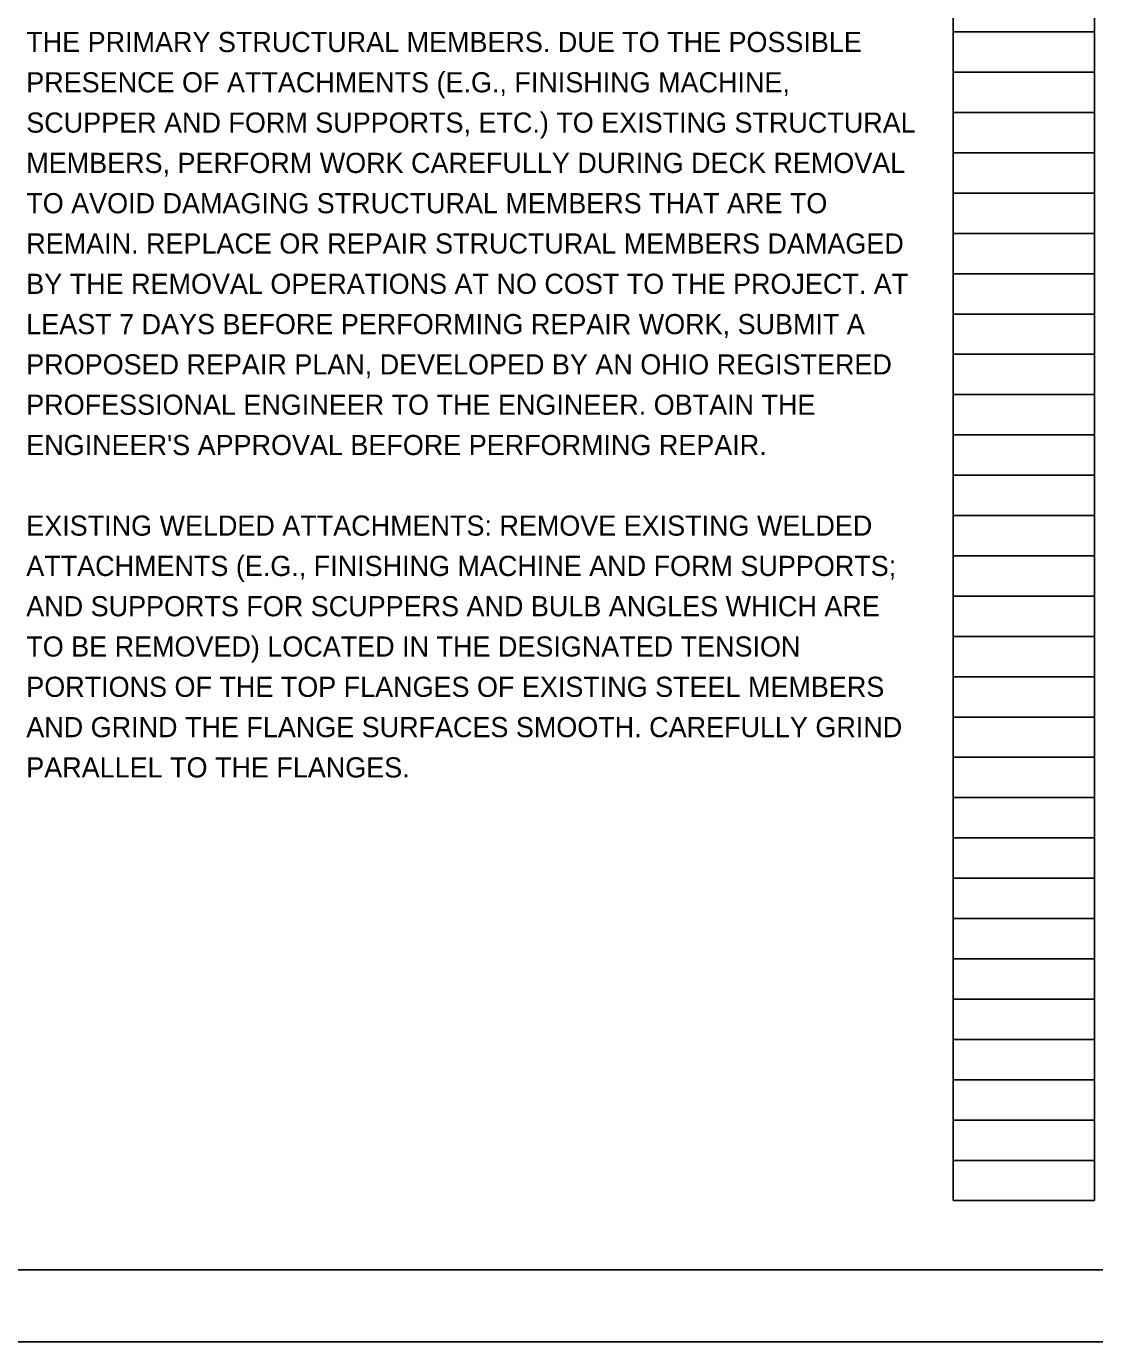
# Model space of a CAD drawing. Extents: x 0 to 34, y 0 to 22.
# Drawn here: x 17.24 to 24.66, y 0 to 9.14 of the extents above; entities that cross this region are included whole.
import ezdxf

# ---------------------------------------------------------------- set-up
doc = ezdxf.new("R2010")
doc.units = 0
for name, color, linetype in [('BR_P_Gen_Text', 7, 'Continuous'), ('SH_Border', 7, 'Continuous'), ('SH_Cut_Line', 7, 'Continuous'), ('SH_Data', 7, 'Continuous')]:
    doc.layers.add(name, color=color, linetype=linetype)

msp = doc.modelspace()

# ---------------------------------------------------------------- linework, layer by layer
at = {"layer": 'SH_Border'}
msp.add_lwpolyline([(1.5, 21.5), (33.5, 21.5), (33.5, 0.5), (1.5, 0.5)], close=True, dxfattribs=at)
at = {"layer": 'SH_Cut_Line'}
msp.add_lwpolyline([(0, 0), (34, 0), (34, 22), (0, 22)], close=True, dxfattribs=at)
at = {"layer": 'SH_Data'}
for p, q in [((23.68, 0.98), (23.68, 21.14)), ((23.68, 0.98), (23.68, 21.14)), ((24.66, 0.98), (24.66, 21.14)), ((24.66, 0.98), (24.66, 21.14)), ((23.68, 9.1), (24.66, 9.1)), ((23.68, 9.1), (24.66, 9.1)), ((23.68, 8.82), (24.66, 8.82)), ((23.68, 8.82), (24.66, 8.82)), ((23.68, 8.54), (24.66, 8.54)), ((23.68, 8.54), (24.66, 8.54)), ((23.68, 8.26), (24.66, 8.26)), ((23.68, 8.26), (24.66, 8.26)), ((23.68, 7.98), (24.66, 7.98)), ((23.68, 7.98), (24.66, 7.98)), ((23.68, 7.7), (24.66, 7.7)), ((23.68, 7.7), (24.66, 7.7)), ((23.68, 7.42), (24.66, 7.42)), ((23.68, 7.42), (24.66, 7.42)), ((23.68, 7.14), (24.66, 7.14)), ((23.68, 7.14), (24.66, 7.14)), ((23.68, 6.86), (24.66, 6.86)), ((23.68, 6.86), (24.66, 6.86)), ((23.68, 6.58), (24.66, 6.58)), ((23.68, 6.58), (24.66, 6.58)), ((23.68, 6.3), (24.66, 6.3)), ((23.68, 6.3), (24.66, 6.3)), ((23.68, 6.02), (24.66, 6.02)), ((23.68, 6.02), (24.66, 6.02)), ((23.68, 5.74), (24.66, 5.74)), ((23.68, 5.74), (24.66, 5.74)), ((23.68, 5.46), (24.66, 5.46)), ((23.68, 5.46), (24.66, 5.46)), ((23.68, 5.18), (24.66, 5.18)), ((23.68, 5.18), (24.66, 5.18)), ((23.68, 4.9), (24.66, 4.9)), ((23.68, 4.9), (24.66, 4.9)), ((23.68, 4.62), (24.66, 4.62)), ((23.68, 4.62), (24.66, 4.62)), ((23.68, 4.34), (24.66, 4.34)), ((23.68, 4.34), (24.66, 4.34)), ((23.68, 4.06), (24.66, 4.06)), ((23.68, 4.06), (24.66, 4.06)), ((23.68, 3.78), (24.66, 3.78)), ((23.68, 3.78), (24.66, 3.78)), ((23.68, 3.5), (24.66, 3.5)), ((23.68, 3.5), (24.66, 3.5)), ((23.68, 3.22), (24.66, 3.22)), ((23.68, 3.22), (24.66, 3.22)), ((23.68, 2.94), (24.66, 2.94)), ((23.68, 2.94), (24.66, 2.94)), ((23.68, 2.66), (24.66, 2.66)), ((23.68, 2.66), (24.66, 2.66)), ((23.68, 2.38), (24.66, 2.38)), ((23.68, 2.38), (24.66, 2.38)), ((23.68, 2.1), (24.66, 2.1)), ((23.68, 2.1), (24.66, 2.1)), ((23.68, 1.82), (24.66, 1.82)), ((23.68, 1.82), (24.66, 1.82)), ((23.68, 1.54), (24.66, 1.54)), ((23.68, 1.54), (24.66, 1.54)), ((23.68, 1.26), (24.66, 1.26)), ((23.68, 1.26), (24.66, 1.26)), ((23.68, 0.98), (24.66, 0.98)), ((23.68, 0.98), (24.66, 0.98))]:
    msp.add_line(p, q, dxfattribs=at)

# ---------------------------------------------------------------- texts
at = {"layer": 'BR_P_Gen_Text'}
for s, p in [('THE PRIMARY STRUCTURAL MEMBERS. DUE TO THE POSSIBLE ', (17.24, 8.96)), ('PRESENCE OF ATTACHMENTS (E.G., FINISHING MACHINE, ', (17.24, 8.68)), ('SCUPPER AND FORM SUPPORTS, ETC.) TO EXISTING STRUCTURAL ', (17.24, 8.4)), ('MEMBERS, PERFORM WORK CAREFULLY DURING DECK REMOVAL ', (17.24, 8.12)), ('TO AVOID DAMAGING STRUCTURAL MEMBERS THAT ARE TO ', (17.24, 7.84)), ('REMAIN. REPLACE OR REPAIR STRUCTURAL MEMBERS DAMAGED ', (17.24, 7.56)), ('BY THE REMOVAL OPERATIONS AT NO COST TO THE PROJECT. AT ', (17.24, 7.28)), ('LEAST 7 DAYS BEFORE PERFORMING REPAIR WORK, SUBMIT A ', (17.24, 7)), ('PROPOSED REPAIR PLAN, DEVELOPED BY AN OHIO REGISTERED ', (17.24, 6.72)), ('PROFESSIONAL ENGINEER TO THE ENGINEER. OBTAIN THE ', (17.24, 6.44)), ("ENGINEER'S APPROVAL BEFORE PERFORMING REPAIR.", (17.24, 6.16)), ('EXISTING WELDED ATTACHMENTS: REMOVE EXISTING WELDED ', (17.24, 5.6)), ('ATTACHMENTS (E.G., FINISHING MACHINE AND FORM SUPPORTS; ', (17.24, 5.32)), ('AND SUPPORTS FOR SCUPPERS AND BULB ANGLES WHICH ARE ', (17.24, 5.04)), ('TO BE REMOVED) LOCATED IN THE DESIGNATED TENSION ', (17.24, 4.76)), ('PORTIONS OF THE TOP FLANGES OF EXISTING STEEL MEMBERS ', (17.24, 4.48)), ('AND GRIND THE FLANGE SURFACES SMOOTH. CAREFULLY GRIND ', (17.24, 4.2)), ('PARALLEL TO THE FLANGES.', (17.24, 3.92))]:
    msp.add_text(s, height=0.14, dxfattribs=at).set_placement(p)

doc.saveas('drawing.dxf')
